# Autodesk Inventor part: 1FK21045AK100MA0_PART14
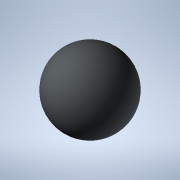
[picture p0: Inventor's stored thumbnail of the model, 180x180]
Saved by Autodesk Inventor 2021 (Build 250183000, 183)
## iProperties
Created: 2025-04
Part Number: 1FK21045AK100MA0_PART14
Material: Generic
Catalog Web Link: www.3dfindit.com
Description: -Servo synchronous motor
Document SubType Name: Modeling
Designer: psAdmin
Mass: 0.137258 g
Surface Area: 1.2868 cm^2
Volume: 0.137258 cm^3
Density: 1 g/cm^3
Appearance: PSOLRGB-212-217-219
Category: PARTsolutions
Title: 1FK21045AK100MA0_PART14
Author: Cadenas PARTsolutions
Comments: Servo synchronous motor
Sending System: PARTsolutions
Preprocessor: ST-DEVELOPER v19.3
PSOL_IDENT_0: {$CADENAS_DATA/23d-libs/siemens_ag/_cat_/e0/5f/1fk21045ak100ma0.prj},216 {VTYP=3D},{NB=1FK21045AK100
PSOL_IDENT_1: MA0_PART14},{LINA=1FK21045AK100MA0_PART14},{NN=1FK21045AK100MA0_PART14},{NOPRJ=TRUE},{DATE=19.08.202
PSOL_IDENT_2: 5 14:01:03},{GEOMDATE=30.07.2025 02:01:57},{VERSION=},{LINEID=10},{WBVAR=},{WBNUMERIC=}  {NB=1FK2104
PSOL_IDENT_3: 5AK100MA0_PART14},{LINA=1FK21045AK100MA0_PART14},{KT=DUMMY},{PREVIEW=../../../_pool_/0f/2c/p_d211_xx
PSOL_IDENT_4: _00438j.png},{DESCSHORT=SIMOTICS S-1FK2 HD, SINAMICS S210 3AC 400V-480V, 1.7 Nm, 6000 rpm},{DESCLONG=
PSOL_IDENT_5: SIMOTICS S-1FK2 HD servo motor M0=2.4 Nm; PN = 1.07 kW at nN=6000 rpm (380-480 V); PN = 0.75 kW at n
PSOL_IDENT_6: N=3000 rpm (200-240 V); with holding brake; degree of protection IP64; cylindrical shaft D19x40mm; a
PSOL_IDENT_7: bsolute encoder 22-bit + 12-bit multiturn (encoder AM22DQC); with OCC interface; plug size M17, rota
PSOL_IDENT_8: table; SIMOTICS S-1FK2 servomotorfor a wide range of uses in industrial environments. SIMOTICS S‑1FK
PSOL_IDENT_9: 2 servomotors are compact synchronous motors with a high dynamic performance that set themselves apa
PSOL_IDENT_10: rt as a result of their high power density, degree of protection and overload capability. The motors
PSOL_IDENT_11: are available in two variants: as High Dynamic variant (highest dynamic performance as a result of
PSOL_IDENT_12: the low intrinsic moment of inertia for applications demanding a high dynamic performance with low m
PSOL_IDENT_13: oved masses) - and as Compact variant (precise and stable closed-loop control for medium up to large
PSOL_IDENT_14: moved masses as a result of a medium intrinsic moment of inertia). SIMOTICSS‑1FK2 servomotors fully
PSOL_IDENT_15: exploit their strengths in a system with the SINAMICSS210 frequency converter and simple connection
PSOL_IDENT_16: using the one cable connection (OCC). Advantages include the short control and positioning times, f
PSOL_IDENT_17: ast and precise correction of disturbing quantities as well as stable control with a high dynamic pe
PSOL_IDENT_18: rformance. The servo motors can be configured to address a wide range of requirements. For example w
PSOL_IDENT_19: ith and without holding brake, IP64 or IP65 degree of protection, singleturn or multiturn absolute e
PSOL_IDENT_20: ncoders - to name just a few. Further, the servomotors are available in different shaft heights exte
PSOL_IDENT_21: nding from 20 to 100. A shaft sealing ring is available to achieve an IP65 degree of protection and
PSOL_IDENT_22: for subsequent mounting at the motor or as spare part. SIMOTICS - the optimum motor for each and eve
PSOL_IDENT_23: ry motion control application.},{INTNO=804766807114},{SUPPLIERALTNO=1FK2104-5AK10-0MA0},{MANUID=1FK2
PSOL_IDENT_24: 1045AK100MA0},{MANUNAME=Siemens},{MANUTYPEDESC=Synchronous motor 1FK2-HD 2,39 Nm},{AAU732=SIMOTICS},
PSOL_IDENT_25: {AAO057=S-1FK2},{AAU734=SIMOTICS S-1FK2 HD servo motor M0=2.4 Nm; PN = 1.07 kW at nN=6000 rpm (380-4
PSOL_IDENT_26: 80 V); PN = 0.75 kW at nN=3000 rpm (200-240 V); with holding brake; degree of protection IP64; cylin
PSOL_IDENT_27: drical shaft D19x40mm; absolute encoder 22-bit + 12-bit multiturn (encoder AM22DQC); with OCC interf
PSOL_IDENT_28: ace; plug size M17, rotatable;},{AAW338=Synchronous motor 1FK2-HD 2,39 Nm},{AAO742=SIMOTICS},{AAO663=
PSOL_IDENT_29: 4042948691236},{NOCUPEROU=1},{PRICEQUANTITY=1},{QUANTITYMIN=1},{QUANTITYINT=1},{CTN=85015100},{COO=D
PSOL_IDENT_30: E},{AAO676=1FK2104-5AK10-0MA0},{AAO677=Siemens AG},{ORDERUNIT=C62},{CONTENTUNIT=C62}
NB: 1FK21045AK100MA0_PART14
NT: Servo synchronous motor
NBSYN: $MANUID._PART14
LINA: 1FK21045AK100MA0_PART14
CATALOG: SIEMENS
PREVIEW: ../../../_pool_/0f/2c/p_d211_xx_00438j.png
DESCSHORT: SIMOTICS S-1FK2 HD, SINAMICS S210 3AC 400V-480V, 1.7 Nm, 6000 rpm
DESCLONG: SIMOTICS S-1FK2 HD servo motor M0=2.4 Nm; PN = 1.07 kW at nN=6000 rpm (380-480 V); PN = 0.75 kW at nN=3000 rpm (200-240 V); with holding brake; degree of protec
INTNO: 804766807114
SUPPLIERALTNO: 1FK2104-5AK10-0MA0
MANUID: 1FK21045AK100MA0
MANUNAME: Siemens
MANUTYPEDESC: Synchronous motor 1FK2-HD 2,39 Nm
AAU732: SIMOTICS
AAO057: S-1FK2
AAU734: SIMOTICS S-1FK2 HD servo motor M0=2.4 Nm; PN = 1.07 kW at nN=6000 rpm (380-480 V); PN = 0.75 kW at nN=3000 rpm (200-240 V); with holding brake; degree of protec
AAW338: Synchronous motor 1FK2-HD 2,39 Nm
AAO742: SIMOTICS
AAO663: 4042948691236.0
NOCUPEROU: 1
PRICEQUANTITY: 1
QUANTITYMIN: 1
QUANTITYINT: 1
CTN: 85015100
COO: DE
ARTICLENO: 1FK21045AK100MA0_PART14
BOMINFO: 1FK21045AK100MA0_PART14
CREATOR: CADENAS GmbH
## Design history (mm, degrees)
feature "2025_04_17_15_45_15_0090"
body "Solid1"
